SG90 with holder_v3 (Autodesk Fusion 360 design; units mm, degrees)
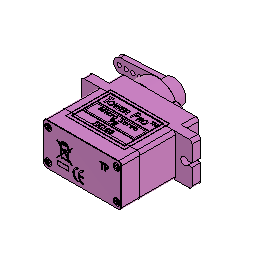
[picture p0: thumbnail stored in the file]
part number: SG90 - Micro Servo 9g - Tower Pro.1
base_feature "Base Feature"
component_insert "Component Insert"
joint "Assemble" alignAngle 0 alignOffsetX 0 alignOffsetY 0 alignOffsetZ 0
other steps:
joint_origin "JointOrigin2"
